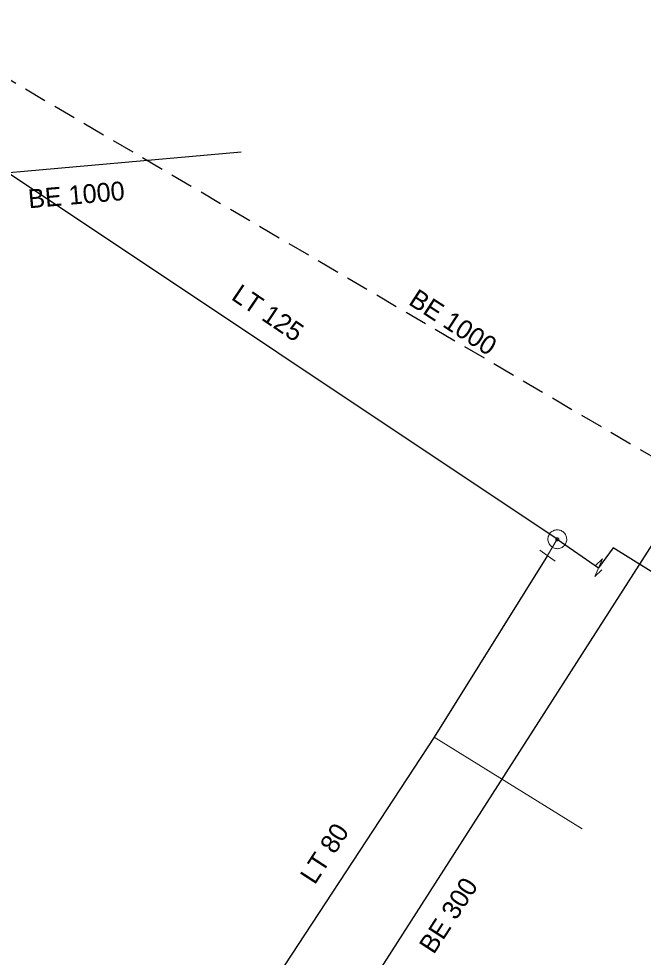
# Model space of a CAD drawing. Extents: x -791337 to -790755, y -988454 to -987923.
# Drawn here: x -791147.53 to -791114.41, y -988018.36 to -987968.58 of the extents above; entities that cross this region are included whole.
import ezdxf

# ---------------------------------------------------------------- set-up
doc = ezdxf.new("R2010")
doc.units = 0
doc.header["$LTSCALE"] = 0.4
doc.linetypes.add('MEDIUM_DASHED', pattern=[4.5, 3, -1.5])
for name, color, linetype, lineweight in [('1', 7, 'Continuous', 13), ('13', 7, 'Continuous', 13), ('14', 7, 'Continuous', 25), ('17', 7, 'Continuous', 25), ('34', 7, 'Continuous', 13), ('47', 7, 'Continuous', 13), ('63', 7, 'MEDIUM_DASHED', 25)]:
    doc.layers.add(name, color=color, linetype=linetype, lineweight=lineweight)

msp = doc.modelspace()

# ---------------------------------------------------------------- linework, layer by layer
at = {"layer": '13'}
msp.add_line((-791125.491, -988006.684), (-791117.647, -988011.546), dxfattribs=at)
at = {"layer": '14', "lineweight": 13}
msp.add_line((-791118.968, -987996.192), (-791119.489, -987997.058), dxfattribs=at)
at = {"layer": '14'}
for points in [[(-791166.588, -988001.112), (-791159.146, -987989.417), (-791151.633, -987977.064), (-791135.73, -987975.64)], [(-791139.701, -988036.706), (-791111.445, -987992.605), (-791110.068, -987992.23)]]:
    msp.add_lwpolyline(points, dxfattribs=at)
at = {"layer": '17'}
for q in [(-791149.767, -987975.656), (-791116.776, -987997.707)]:
    msp.add_line((-791118.968, -987996.192), q, dxfattribs=at)
for points in [[(-791095.362, -988011.495), (-791094.625, -988010.232), (-791095.929, -988009.462), (-791112.248, -987998.984), (-791116.006, -987996.647), (-791116.776, -987997.707)], [(-791119.489, -987997.058), (-791125.491, -988006.684), (-791133.785, -988019.338), (-791141.949, -988031.239), (-791142.416, -988031.808)]]:
    msp.add_lwpolyline(points, dxfattribs=at)
at = {"layer": '34'}
msp.add_line((-791119.896, -987996.768), (-791119.082, -987997.348), dxfattribs=at)
at = {"layer": '47'}
msp.add_line((-791116.572, -987997.239), (-791116.941, -987997.592), dxfattribs=at)
for points in [[(-791118.598, -987995.855), (-791118.635, -987995.818), (-791118.676, -987995.785), (-791118.72, -987995.758), (-791118.767, -987995.734), (-791118.816, -987995.715), (-791118.867, -987995.702), (-791118.919, -987995.695), (-791118.971, -987995.692), (-791119.023, -987995.695), (-791119.075, -987995.703), (-791119.126, -987995.717), (-791119.174, -987995.737), (-791119.22, -987995.76), (-791119.264, -987995.789), (-791119.304, -987995.822), (-791119.341, -987995.859), (-791119.374, -987995.9), (-791119.402, -987995.945), (-791119.425, -987995.991), (-791119.444, -987996.04), (-791119.457, -987996.091), (-791119.465, -987996.143), (-791119.467, -987996.195), (-791119.465, -987996.247), (-791119.456, -987996.299), (-791119.442, -987996.35), (-791119.423, -987996.399), (-791119.399, -987996.444), (-791119.37, -987996.488), (-791119.337, -987996.528), (-791119.3, -987996.565), (-791119.259, -987996.598), (-791119.215, -987996.627), (-791119.168, -987996.649), (-791119.119, -987996.668), (-791119.069, -987996.682), (-791119.017, -987996.69), (-791118.964, -987996.692), (-791118.912, -987996.689), (-791118.86, -987996.68), (-791118.809, -987996.666), (-791118.761, -987996.648), (-791118.715, -987996.623), (-791118.671, -987996.594), (-791118.631, -987996.561), (-791118.594, -987996.524), (-791118.561, -987996.483), (-791118.533, -987996.439), (-791118.51, -987996.392), (-791118.491, -987996.343), (-791118.477, -987996.293), (-791118.47, -987996.241), (-791118.468, -987996.189), (-791118.471, -987996.136), (-791118.479, -987996.084), (-791118.493, -987996.033), (-791118.512, -987995.986), (-791118.536, -987995.939), (-791118.565, -987995.895)], [(-791118.907, -987996.136), (-791118.913, -987996.13), (-791118.92, -987996.125), (-791118.927, -987996.12), (-791118.934, -987996.117), (-791118.943, -987996.113), (-791118.951, -987996.112), (-791118.96, -987996.11), (-791118.968, -987996.109), (-791118.977, -987996.11), (-791118.985, -987996.111), (-791118.994, -987996.114), (-791119.002, -987996.117), (-791119.009, -987996.121), (-791119.016, -987996.125), (-791119.023, -987996.131), (-791119.029, -987996.137), (-791119.034, -987996.144), (-791119.039, -987996.151), (-791119.042, -987996.158), (-791119.046, -987996.167), (-791119.047, -987996.175), (-791119.049, -987996.184), (-791119.05, -987996.192), (-791119.049, -987996.201), (-791119.048, -987996.209), (-791119.045, -987996.218), (-791119.042, -987996.226), (-791119.038, -987996.233), (-791119.034, -987996.24), (-791119.028, -987996.247), (-791119.022, -987996.253), (-791119.015, -987996.258), (-791119.008, -987996.263), (-791119.001, -987996.266), (-791118.992, -987996.27), (-791118.985, -987996.272), (-791118.975, -987996.273), (-791118.967, -987996.274), (-791118.958, -987996.273), (-791118.95, -987996.272), (-791118.941, -987996.269), (-791118.933, -987996.266), (-791118.926, -987996.262), (-791118.919, -987996.258), (-791118.912, -987996.252), (-791118.906, -987996.246), (-791118.901, -987996.239), (-791118.896, -987996.232), (-791118.893, -987996.225), (-791118.889, -987996.216), (-791118.887, -987996.209), (-791118.886, -987996.199), (-791118.885, -987996.191), (-791118.886, -987996.182), (-791118.887, -987996.174), (-791118.89, -987996.165), (-791118.893, -987996.157), (-791118.897, -987996.15), (-791118.901, -987996.143)]]:
    msp.add_lwpolyline(points, close=True, dxfattribs=at)
msp.add_lwpolyline([(-791116.572, -987997.239), (-791116.979, -987998.174), (-791116.61, -987997.821)], dxfattribs=at)
at = {"layer": '63'}
msp.add_lwpolyline([(-791231.02, -987923.132), (-790755.118, -988202.253), (-790755.118, -988202.253), (-790903.053, -988400.429), (-790903.053, -988400.429), (-791331.504, -988073.857), (-791331.504, -988073.857)], close=True, dxfattribs=at)

# ---------------------------------------------------------------- texts
at = {"layer": '1'}
for s, rotation, p in [('BE 1000 ', 5, (-791146.99, -987978.641)), ('LT 125', 326, (-791136.317, -987983.439)), ('BE 1000 ', 327, (-791126.915, -987983.701)), ('LT 80 ', 57, (-791131.832, -988014.561)), ('BE 300', 57, (-791125.519, -988018.252))]:
    msp.add_text(s, height=1, rotation=rotation, dxfattribs=at).set_placement(p)

doc.saveas('drawing.dxf')
